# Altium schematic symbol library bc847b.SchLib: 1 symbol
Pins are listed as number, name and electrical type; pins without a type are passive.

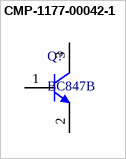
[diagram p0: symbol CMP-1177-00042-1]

## CMP-1177-00042-1
designator Q?, comment BC847B
NPN Silicon AF Transistor, 45 V VCEO, 100 mA IC, SOT23, Reel, Green; Manufacturer: Infineon; VEBO (max): 6Â V; ICBO (max): 15Â nA; VCBO (max): 50Â V; IBM (max): 200Â mA; Green: TRUE; Ptot (max): 330Â mW; fT (typ): 250Â MHz; IC (max): 100Â mA; VCEO (max): 45Â V
footprint INF-SOT23_L (SOT23, 3-Leads, Body 2.9x1.3 mm, Pitch 0.95 mm, IPC High Density)
footprint INF-SOT23_M (SOT23, 3-Leads, Body 2.9x1.3 mm, Pitch 0.95 mm, IPC Low Density)
footprint INF-SOT23_N (SOT23, 3-Leads, Body 2.9x1.3 mm, Pitch 0.95 mm, IPC Medium Density)
pins: 1 B, 2 E, 3 C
